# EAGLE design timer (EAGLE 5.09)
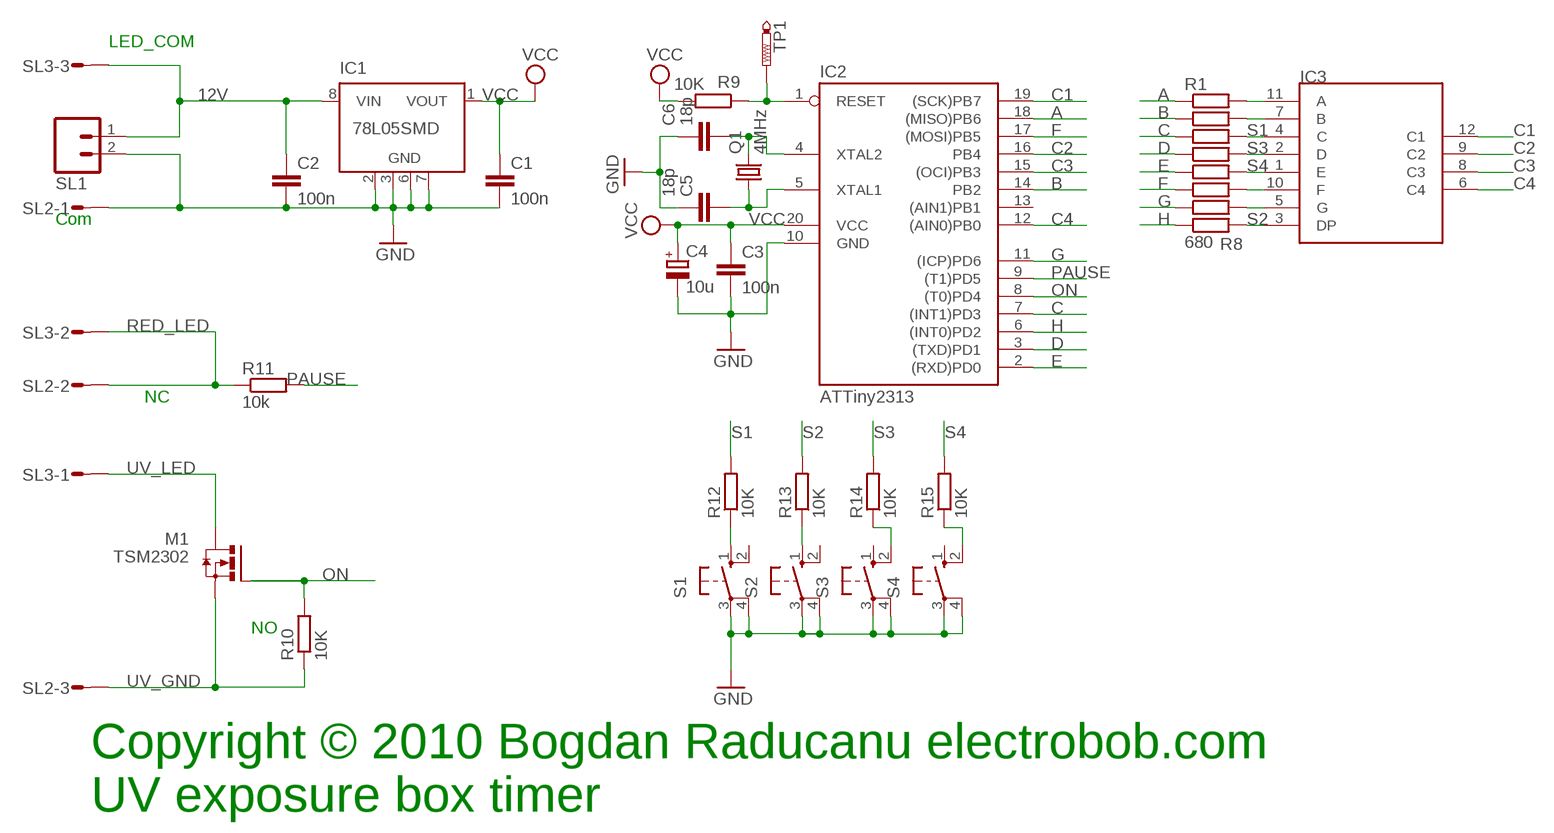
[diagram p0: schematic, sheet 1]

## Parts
C1  100n  C-EUC0805K  [C0805K]
C2  100n  C-EUC0805K  [C0805K]
C3  100n  C-EUC0805K  [C0805K]
C4  10u  CPOL-EUSMCA  [SMC_A]
C5  18p  C-EUC0805K  [C0805K]
C6  18p  C-EUC0805K  [C0805K]
IC1  78L05SMD  [SO08]
IC2  ATTiny2313  AT90S2313S  [SO20L]
IC3  KW4-361ASB  [KW4]
M1  TSM2302  IRLML  [MICRO3]
Q1  4MHz  CRYSTALHC49S  [HC49/S]
R1  680  R-EU_M0805  [M0805]
R2  680  R-EU_M0805  [M0805]
R3  680  R-EU_M0805  [M0805]
R4  680  R-EU_M0805  [M0805]
R5  680  R-EU_M0805  [M0805]
R6  680  R-EU_M0805  [M0805]
R7  680  R-EU_M0805  [M0805]
R8  680  R-EU_M0805  [M0805]
R9  10K  R-EU_M0805  [M0805]
R10  10K  R-EU_M0805  [M0805]
R11  10k  R-EU_M0805  [M0805]
R12  10K  R-EU_M0805  [M0805]
R13  10K  R-EU_M0805  [M0805]
R14  10K  R-EU_M0805  [M0805]
R15  10K  R-EU_M0805  [M0805]
S1  10-XX  [B3F-10XX]
S2  10-XX  [B3F-10XX]
S3  10-XX  [B3F-10XX]
S4  10-XX  [B3F-10XX]
SL1  MA02  [02PA]
SL2  MA03S  [03PA]
SL3  MA03S  [03PA]
TP1  PTR1TP10R  [TP10R]

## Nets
12V: C2.1 IC1.8(VIN) SL1.1 SL3.3
A: IC2.18((MISO)PB6) R1.1
B: IC2.14(PB2) R2.1
C: IC2.7((INT1)PD3) R3.1
C1: IC2.19((SCK)PB7) IC3.12(C1)
C2: IC2.16(PB4) IC3.9(C2)
C3: IC2.15((OCI)PB3) IC3.8(C3)
C4: IC2.12((AIN0)PB0) IC3.6(C4)
D: IC2.3((TXD)PD1) R4.1
E: IC2.2((RXD)PD0) R5.1
F: IC2.17((MOSI)PB5) R6.1
G: IC2.11((ICP)PD6) R7.1
GND: C1.2 C2.2 C3.2 C4.- C5.1 C6.1 IC1.2(GND) IC1.3(GND) IC1.6(GND) IC1.7(GND) IC2.10(GND) S1.3(P) S1.4(P1) S2.3(P) S2.4(P1) S3.3(P) S3.4(P1) S4.3(P) S4.4(P1) SL1.2 SL2.1
H: IC2.6((INT0)PD2) R8.1
N$1: R12.1 S1.1(S)
N$2: R13.1 S2.1(S)
N$3: R14.1 S3.2(S1)
N$4: R15.1 S4.2(S1)
N$5: C6.2 IC2.4(XTAL2) Q1.2
N$6: C5.2 IC2.5(XTAL1) Q1.1
N$12: IC3.11(A) R1.2
N$13: IC3.7(B) R2.2
N$17: IC3.10(F) R6.2
N$18: IC3.5(G) R7.2
N$32: IC2.1(RESET) R9.1 TP1.TP
ON: IC2.8((T0)PD4) M1.1(G) R10.2
PAUSE: IC2.9((T1)PD5) R11.2
RED_LED: R11.1 SL2.2 SL3.2
S1: IC3.4(C) R3.2 R12.2
S2: IC3.3(DP) R8.2 R13.2
S3: IC3.2(D) R4.2 R14.2
S4: IC3.1(E) R5.2 R15.2
UV_GND: M1.2(S) R10.1 SL2.3
UV_LED: M1.3(D) SL3.1
VCC: C1.1 C3.1 C4.+ IC1.1(VOUT) IC2.20(VCC) R9.2
Unconnected: IC1.4(NC) IC1.5(NC) IC2.13((AIN1)PB1) S1.2(S1) S2.2(S1) S3.1(S) S4.1(S)

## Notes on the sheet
- LED_COM
- Com
- NC
- NO
- Copyright © 2010 Bogdan Raducanu electrobob.com
- UV exposure box timer

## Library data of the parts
C1-C3 C5 C6 = rcl:C-EU: CAPACITOR, European symbol
C4 = rcl:CPOL-EU: POLARIZED CAPACITOR, European symbol
IC1 = linear:78L*SMD: Positive VOLTAGE REGULATOR
IC2 = atmel:AT90S2313: MICROCONTROLLER 2 Kbytes FLASH 128 bytes SRAM 128 bytes EEPROM UART
IC3 = luckylight:KW4-361ASB
M1 = transistor-power:IRLML
Q1 = crystal:CRYSTAL: CRYSTAL
R1-R15 = rcl:R-EU_: RESISTOR, European symbol
S1-S4 = switch-omron:10-XX: OMRON SWITCH
SL1 = con-amp-quick:MA02: AMP QUICK CONNECTOR
SL2 SL3 = con-amp-quick:MA03S: AMP QUICK CONNECTOR
TP1 = testpad:PTR1: TEST PIN

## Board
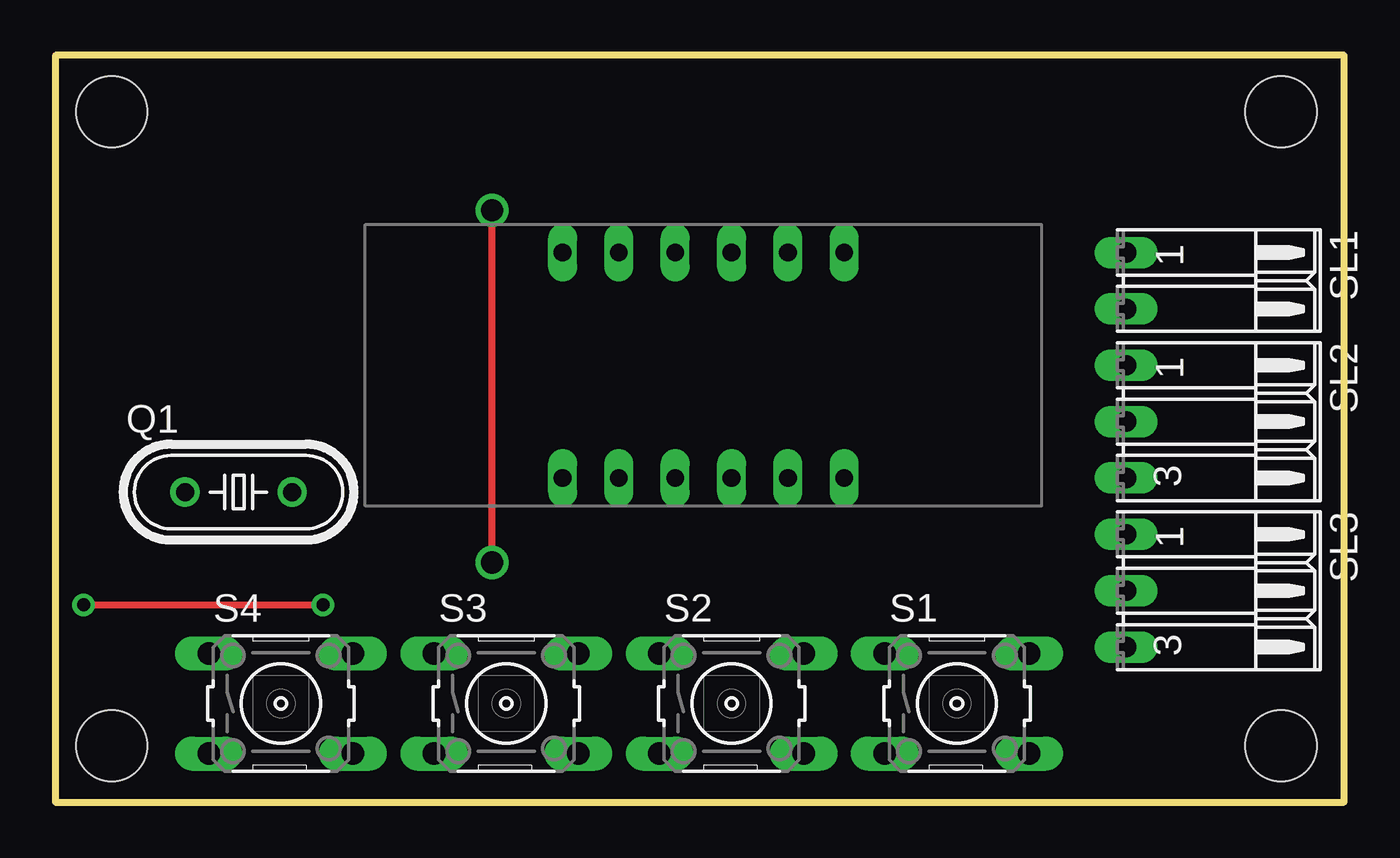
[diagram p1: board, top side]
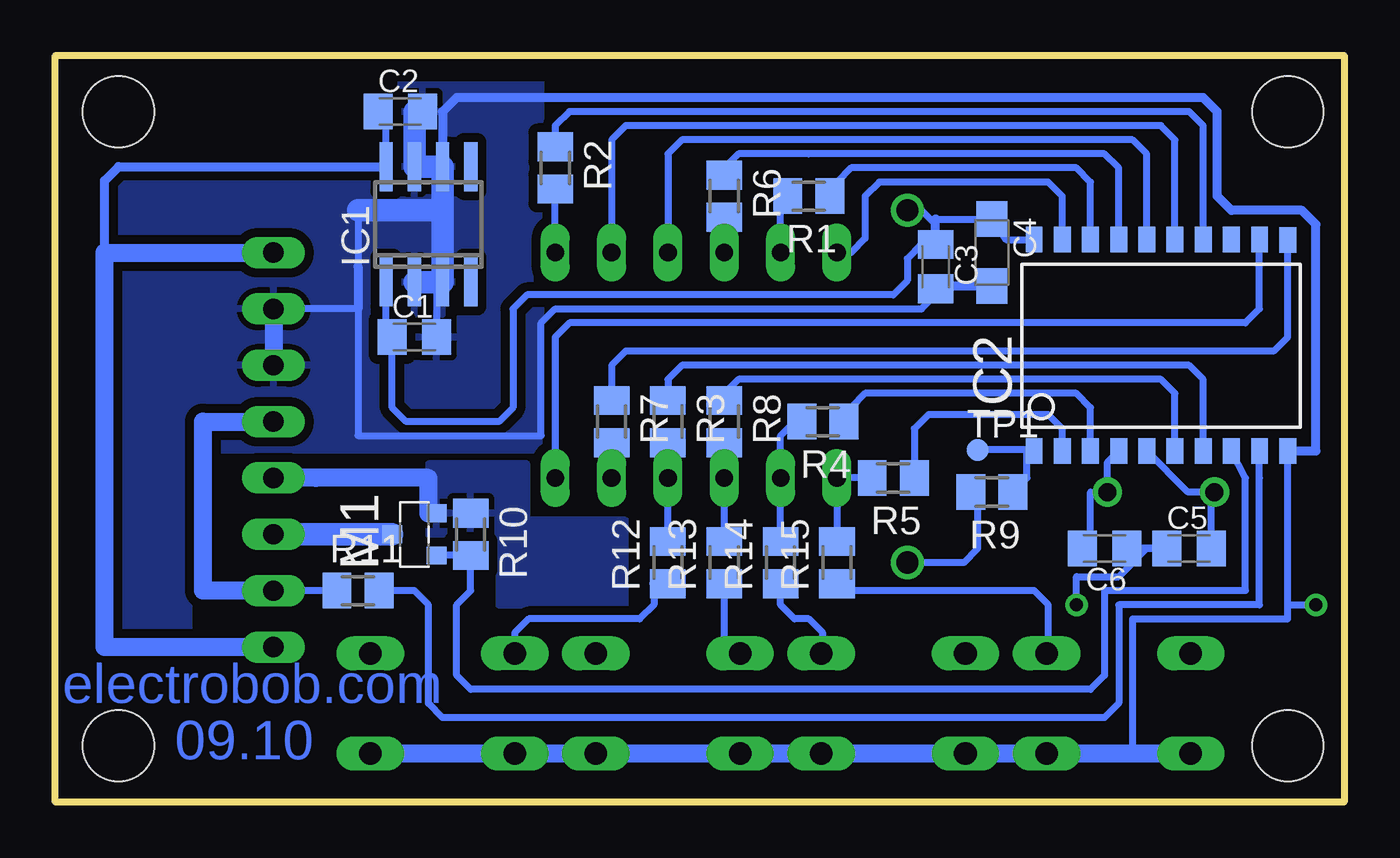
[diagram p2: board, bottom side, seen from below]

Size 58.09 x 33.65 mm. Coordinates in mm from the lower left corner, seen from the top.
Outline: 0,0 58.09,0 58.09,33.65 0,33.65 0,0
Copper layers (1*16): Top 0.035mm / dielectric 1.5mm / Bottom 0.035mm
Design rules "pcboards": minimum track width 0.2mm, minimum drill 0.3mm, track to track 0.2mm, track to pad 0.25mm, pad to pad 0.25mm, via to via 0.25mm, smd to smd 0.2mm, copper to edge 40mil, drill to drill 8mil, minimum pad ring 10mil, minimum via ring 8mil, stop-mask expansion 4mil, vias tented up to drill 0mil, thermal gap 10mil
Holes 3.2 mm at 2.54,2.54 2.54,31.11 55.24,31.11 55.24,2.54

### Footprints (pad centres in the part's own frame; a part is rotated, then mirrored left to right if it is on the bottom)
C0805K = smd 1.3 x 1.6: 1 -1,0; 2 1,0
SMC_A = smd 1.6 x 1.4: + -1.5,0; - 1.5,0
SO08 = smd 0.6 x 2.2: 1 -1.905,-2.6; 2 -0.635,-2.6; 3 0.635,-2.6; 4 1.905,-2.6; 5 1.905,2.6; 6 0.635,2.6; 7 -0.635,2.6; 8 -1.905,2.6
SO20L = smd 0.762 x 1.143: 1 -5.08,-5.131; 2 -3.81,-5.131; 3 -2.54,-5.131; 4 -1.27,-5.131; 5 0,-5.131; 6 1.27,-5.131; 7 2.54,-5.131; 8 3.81,-5.131; 9 5.08,-5.131; 10 6.35,-5.131; 11 6.35,4.369; 12 5.08,4.394; 13 3.81,4.394; 14 2.54,4.394; 15 1.27,4.394; 16 0,4.394; 17 -1.27,4.394; 18 -2.54,4.394; 19 -3.81,4.394; 20 -5.08,4.394
KW4 = drill 0.8 long: 1 -6.35,-5.08; 2 -3.81,-5.08; 3 -1.27,-5.08; 4 1.27,-5.08; 5 3.81,-5.08; 6 6.35,-5.08; 7 6.35,5.08; 8 3.81,5.08; 9 1.27,5.08; 10 -1.27,5.08; 11 -3.81,5.08; 12 -6.35,5.08
MICRO3 = smd 0.8 x 0.9: 1 -0.95,-1; 2 0.95,-1; 3 0,1
HC49/S = drill 0.813 round: 1 -2.413,0; 2 2.413,0
M0805 = smd 1.3 x 1.6: 1 -0.95,0; 2 0.95,0
B3F-10XX = drill 1.016 long: 1 -3.251,2.261; 2 3.251,2.261; 3 -3.251,-2.261; 4 3.251,-2.261
02PA = drill 0.914 long: 1 -1.27,0; 2 1.27,0
03PA = drill 0.914 long: 1 -2.54,0; 2 0,0; 3 2.54,0
TP10R = smd 1 x 1: TP 0,0

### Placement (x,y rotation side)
C1  41.91,20.95 0 bottom
C2  42.55,31.11 0 bottom
C3  18.41,24.13 270 bottom
C4  15.88,24.77 270 bottom
C5  6.99,11.43 0 bottom
C6  10.79,11.43 180 bottom
IC1  41.27,26.04 0 bottom
IC2  8.89,20.95 0 bottom
IC3  29.21,19.68 0 top
M1  41.91,12.06 90 bottom
Q1  8.26,13.97 0 top
R1  24.13,27.3 180 bottom
R2  35.56,28.57 270 bottom
R3  30.48,17.14 270 bottom
R4  23.5,17.14 180 bottom
R5  20.32,14.61 180 bottom
R6  27.94,27.3 270 bottom
R7  33.02,17.14 270 bottom
R8  27.94,17.14 270 bottom
R9  15.88,13.97 180 bottom
R10  39.37,12.06 270 bottom
R11  44.45,9.53 0 bottom
R12  30.48,10.79 90 bottom
R13  27.94,10.79 90 bottom
R14  25.4,10.79 90 bottom
R15  22.86,10.79 90 bottom
S1  40.64,4.45 0 top
S2  30.48,4.45 0 top
S3  20.32,4.45 0 top
S4  10.16,4.45 0 top
SL1  48.26,23.5 270 top
SL2  48.26,17.14 270 top
SL3  48.26,9.53 270 top
TP1  16.51,15.88 0 bottom

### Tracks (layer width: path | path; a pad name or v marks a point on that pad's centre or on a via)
12V
  Bottom 0.305: C2.1 43.18,31.75 IC1.8
  Bottom 0.406: 55.88,24.77 55.88,28 55.24,28.64 IC1.8
  Bottom 0.813: SL1.1 55.88,24.77 55.88,12.06 55.88,6.99 SL3.3
A
  Bottom 0.305: 22.86,27.3 22.86,27.94 22.23,28.57 12.06,28.57 11.43,27.94 IC2.18
  Bottom 0.406: 22.86,27.3 R1.1
B
  Bottom 0.305: R2.1 35.56,30.48 34.92,31.11 6.99,31.11 6.35,30.48 IC2.14
C
  Bottom 0.305: IC2.7 6.35,19.05 6.99,19.68 29.84,19.68 30.48,19.05 R3.1
C1
  Bottom 0.305: IC2.19 12.7,27.3 13.34,27.94 20.95,27.94 21.59,27.3 21.59,25.4 22.23,24.77 IC3.12
C2
  Bottom 0.305: IC3.9 30.48,29.21 29.84,29.84 9.53,29.84 8.89,29.21 IC2.16
C3
  Bottom 0.305: IC3.8 33.02,29.84 32.38,30.48 8.26,30.48 7.62,29.84 IC2.15
C4
  Bottom 0.305: IC3.6 35.56,20.95 34.92,21.59 4.45,21.59 3.81,22.23 IC2.12
D
  Bottom 0.305: IC2.3 11.43,17.78 12.06,18.41 21.59,18.41 22.23,17.78 22.23,17.14
  Bottom 0.406: 22.23,17.14 R4.1
E
  Bottom 0.305: IC2.2 12.7,16.82 13.34,17.46 18.73,17.46 19.37,16.82 R5.1
F
  Bottom 0.305: IC2.17 10.16,28.57 10.79,29.21 24.13,29.21 27.3,29.21 27.94,28.57 R6.1
G
  Bottom 0.305: R7.1 33.02,19.68 32.38,20.32 5.08,20.32 3.17,20.32 2.54,20.95 IC2.11
GND  (via drill 0.6 pad 1.02)
  Top 0.305: v1.27,8.89 v12.06,8.89
  Bottom 0.305: 44.45,22.23 SL1.2 | C3.2 18.41,22.86 19.05,22.23 35.56,22.23 36.2,21.59 36.2,16.51 44.45,16.51 44.45,22.23 | 44.45,22.23 44.45,24.13 44.45,26.67 | S4.3 9.53,2.18 9.53,8.26 8.26,8.26 2.54,8.26 2.54,8.89 | 2.54,8.89 2.54,11.43 IC2.10 | IC1.3 40.91,23.43 C1.2 | 41.91,31.11 C2.2 | C6.1 C5.1 8.89,11.43 10.16,10.16 12.06,10.16 v12.06,8.89 | 2.54,8.89 v1.27,8.89
  Bottom 0.406: C4.- 18.41,23.27 C3.2 | 44.45,24.13 44.45,22.23 | IC2.10 1.27,15.82 1.27,26.04 1.91,26.67 5.08,26.67 5.71,27.3 5.71,31.11 6.35,31.75 36.83,31.75 40.01,31.75 40.64,31.11 IC1.6
  Bottom 0.813: SL1.2 SL2.1 | S1.4 S1.3 S2.4 S2.3 S3.4 S3.3 S4.4 9.53,2.18 S4.3
  Bottom 1.016: 40.64,26.67 IC1.3 IC1.2 | 40.64,26.67 IC1.6 IC1.7 41.91,31.11 | 40.64,26.67 44.45,26.67
  pour Bottom (isolate 0.406): 36.2,33.66 57.78,33.66 57.78,6.99 52.07,6.99 52.07,15.88 36.2,15.88
H
  Bottom 0.305: IC2.6 7.62,18.41 8.26,19.05 27.3,19.05 27.94,18.41 R8.1
N$1
  Bottom 0.305: 31.11,9.85 31.11,8.89 31.75,8.26 36.75,8.26 37.39,7.62 S1.1
  Bottom 0.406: R12.1 31.11,9.85
N$2
  Bottom 0.305: S2.1 27.3,6.71 27.94,7.34 R13.1
N$3
  Bottom 0.305: 23.5,6.71 23.5,7.62 24.13,8.26 24.77,8.26 25.4,8.89 R14.1
  Bottom 0.406: S3.2 23.5,6.71
N$4
  Bottom 0.305: 13.34,6.71 13.34,8.89 13.97,9.53 22.86,9.53
  Bottom 0.406: S4.2 13.34,6.71 | 22.86,9.53 R15.1
N$5
  Bottom 0.305: IC2.4 10.67,15.32 Q1.2 11.43,13.97 11.43,11.79 C6.2
N$6
  Bottom 0.305: IC2.5 7.04,13.97 Q1.1 5.99,13.83 C5.2
N$12
  Bottom 0.305: IC3.11 25.4,27.3
  Bottom 0.406: 25.4,27.3 R1.2
N$13
  Bottom 0.305: IC3.7 R2.2
N$17
  Bottom 0.305: IC3.10 R6.2
N$18
  Bottom 0.305: IC3.5 R7.2
N$32
  Bottom 0.305: R9.1 14.29,14.61 14.29,15.82 IC2.1 14.02,15.88 TP1.TP
ON
  Bottom 0.305: IC2.8 4.45,14.61 4.45,9.53 10.16,9.53 10.79,9.53 10.79,5.71 11.43,5.08 39.37,5.08 40.01,5.71 40.01,8.89 39.37,9.53 R10.2 M1.1
PAUSE
  Bottom 0.305: IC2.9 3.81,14.61 3.81,8.89 10.16,8.89 10.16,4.45 10.79,3.81 40.64,3.81 41.27,4.45 41.27,8.89 41.91,9.53 43.18,9.53
  Bottom 0.406: 43.18,9.53 R11.2
RED_LED
  Bottom 0.305: R11.1 SL3.2
  Bottom 0.813: SL2.2 51.44,17.14 51.44,14.61 51.44,9.53 SL3.2
S1
  Bottom 0.305: R3.2 IC3.4 R12.2
S2
  Bottom 0.305: R8.2 IC3.3 R13.2
S3
  Bottom 0.305: R14.2 IC3.2 25.4,16.51 24.77,17.14 R4.2
S4
  Bottom 0.305: R15.2 IC3.1 R5.2
UV_GND
  Bottom 0.813: M1.2 41.27,13.02 41.27,14.61 46.35,14.61 SL2.3
  pour Bottom (isolate 0.406): 41.27,15.24 41.27,12.06 38.1,12.06 38.1,8.89 32.38,8.89 32.38,12.7 36.83,12.7 36.83,15.24
UV_LED
  Bottom 1.016: M1.3 SL3.1
VCC  (via drill 1, 1 pad 1.02)
  Top 0.305: v19.68,10.79 v19.68,26.67
  Bottom 0.305: IC2.20 15.24,25.35 C4.+ 18.41,26.27 | 19.05,25.13 19.68,24.5 19.68,23.5 20.32,22.86 36.83,22.86 37.47,22.23 37.47,17.78 38.1,17.14 42.27,17.14 42.91,17.78 C1.1 | 43.18,20.95 IC1.1 | v19.68,26.67 19.05,26.67 18.41,26.04 C3.1 | v19.68,10.79 17.14,10.79 16.51,11.43 16.51,13.34 16.51,13.65 R9.2
  Bottom 0.406: 18.41,26.27 C3.1 19.05,25.13 | C1.1 43.18,20.95

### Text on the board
Bottom: electrobob.com | 09.10
tDocu: UV BOX TIMER | VCC | GND | COM | NC | NO | UV | RED | START/PAUSE | UP | DOWN | MEM | LED_C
